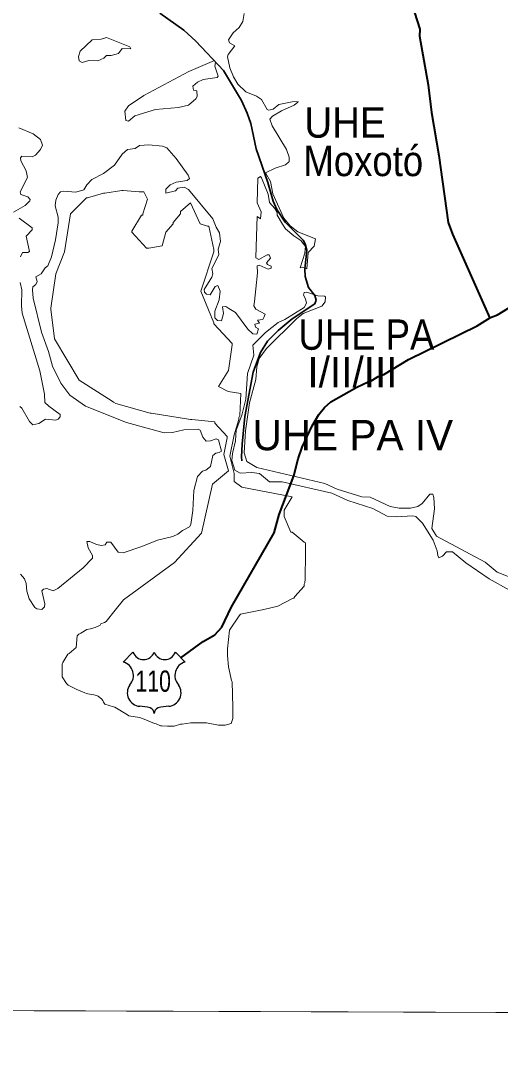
# Model space of a CAD drawing. Extents: x 553962 to 842807, y 8883888 to 9032388.
# Drawn here: x 580395 to 581976, y 8909822 to 8913255 of the extents above; entities that cross this region are included whole.
import ezdxf
from ezdxf.enums import TextEntityAlignment as Align

# ---------------------------------------------------------------- set-up
doc = ezdxf.new("R2010")
doc.units = 0
doc.header["$LTSCALE"] = 200
doc.linetypes.add('LONG_DASH_SHORT_DASH', pattern=[9.9, 6, -1.2, 1.5, -1.2])
doc.layers.add('6', color=7, linetype='Continuous', lineweight=13)

msp = doc.modelspace()

# ---------------------------------------------------------------- linework, layer by layer
at = {"layer": '6', "lineweight": 25}
for p, q in [((580732.9, 8911139.1), (580764.9, 8911171.1)), ((580904.8, 8911171.1), (580936.8, 8911139.1))]:
    msp.add_line(p, q, dxfattribs=at)
at = {"layer": '6'}
msp.add_line((574653.9, 8910009.3), (626625.7, 8909822.1), dxfattribs=at)
for points in [[(585645.8, 8921027.3), (574684.9, 8921064.7), (574653.9, 8910009.3), (585614.8, 8909969.8)], [(580677.4, 8913199.3), (580754.6, 8913169.1), (580757.7, 8913161.8), (580729.4, 8913163.2), (580717.7, 8913147), (580692.7, 8913140.2), (580677.9, 8913140.2), (580669, 8913131.7), (580648.6, 8913122.4), (580619.7, 8913123.6), (580597.1, 8913117.7), (580587.8, 8913122.8), (580585.2, 8913136.5), (580590.4, 8913155), (580629.9, 8913192.5), (580660.4, 8913193.7)], [(580749.7, 8912974.1), (580801.2, 8913008.5), (580948.9, 8913087.1), (581033.9, 8913124), (581037.3, 8913116.8), (581035.2, 8913105.4), (581045.7, 8913072.2), (581042.7, 8913067.9), (580996, 8913061.1), (580977.8, 8913051.8), (580962.2, 8913039.1), (580964.6, 8913025.5), (580976, 8913023.8), (580976.9, 8913004.7), (580972.7, 8912997.5), (580948.1, 8912976.6), (580915.4, 8912968.6), (580838.8, 8912961.7), (580770.9, 8912941.3), (580750.1, 8912923.1), (580741.6, 8912925.3), (580737.8, 8912956.3)]]:
    msp.add_lwpolyline(points, close=True, dxfattribs=at)
at = {"layer": '6', "linetype": 'LONG_DASH_SHORT_DASH', "lineweight": 35}
msp.add_lwpolyline([(580854, 8913279.9), (580932.2, 8913223.8), (580972.1, 8913187.7), (581063.2, 8913090.6), (581122.5, 8912991.5), (581142, 8912949.8), (581153.2, 8912915.6), (581171, 8912832.2), (581209.9, 8912721.7), (581227.6, 8912659.4), (581239.2, 8912631.8), (581266.5, 8912590.3), (581326.2, 8912531.5), (581332.6, 8912519.4), (581337.8, 8912498.5), (581331.8, 8912436.4), (581333.1, 8912411.1), (581343.9, 8912375), (581365.1, 8912348.2), (581368.5, 8912332.5), (581364.2, 8912321.3), (581289.9, 8912271.7), (581243.5, 8912233.1), (581208.6, 8912197.7), (581185.2, 8912160.5), (581161.6, 8912095.9), (581134.3, 8911949.1), (581124.7, 8911857.9), (581122.5, 8911815.6), (581124, 8911803.1)], dxfattribs=at)
at = {"layer": '6'}
for points in [[(581309.8, 8912988.2), (581309.8, 8912988.2), (581289.7, 8912987.7), (581245.5, 8912978.7), (581227.2, 8912963.4), (581212, 8912960.1), (581207.2, 8912962.6), (581188.9, 8912994.9), (581172.8, 8913005.9), (581137.1, 8913019.9), (581110.7, 8913045.9), (581096, 8913070), (581084, 8913099.8), (581076.8, 8913135.4), (581079.3, 8913144), (581100.6, 8913172.4), (581083.2, 8913182.3), (581079.8, 8913192.1), (581095.1, 8913214.9), (581115, 8913232.4), (581127.7, 8913252.7), (581131.6, 8913278.4)], [(581277.8, 8912788.2), (581279.5, 8912789.6), (581280, 8912805.1), (581271, 8912830.4), (581223.8, 8912908.6), (581216.6, 8912930.4), (581224.7, 8912939.7), (581254.8, 8912957.9), (581296.7, 8912976.6), (581308.1, 8912986.6), (581309.8, 8912988.2)], [(580388.5, 8912901.4), (580436.2, 8912882.3), (580460.3, 8912862.7), (580466.7, 8912844), (580460.3, 8912829.6), (580443.8, 8912811), (580432.7, 8912806.3), (580397.9, 8912807.9), (580394.1, 8912802.5), (580395.3, 8912793), (580413.2, 8912759.9), (580416.6, 8912737.9), (580392.8, 8912690.9), (580395.3, 8912681.4), (580418.7, 8912673.7), (580425.9, 8912664.7), (580424.9, 8912660.4), (580409.4, 8912645.7), (580371.5, 8912623.9)], [(580896.6, 8911553.8), (580912.7, 8911561), (580928, 8911573.3), (580951, 8911585.2), (580955.3, 8911593.3), (580962.1, 8911639.2), (580965.5, 8911704.7), (580977.3, 8911751.3), (580993.9, 8911768.7), (581005.5, 8911772.6), (581020.3, 8911784.5), (581028.3, 8911821), (581038.6, 8911828.7), (581049.6, 8911829.9), (581056.8, 8911835.1), (581046.7, 8911872.7), (581039.4, 8911875.4), (581020.8, 8911869.1), (581005.8, 8911868.2), (580995.2, 8911881.4), (580986.3, 8911903.8), (580980.3, 8911907.2), (580933.2, 8911905.1), (580895.8, 8911896.2), (580867.6, 8911895.4), (580743.7, 8911929.8), (580608.6, 8911983.8), (580557.2, 8912019.4), (580527, 8912059), (580499.4, 8912115), (580486.1, 8912163.4), (580463.7, 8912227.1), (580435.7, 8912339.3), (580433.1, 8912367.4), (580435.2, 8912376.6), (580444.6, 8912384.8), (580449.3, 8912394.6), (580444.7, 8912409.9), (580462.4, 8912419.7), (580475.2, 8912439.6), (580484.5, 8912446.8), (580496.3, 8912475.7), (580510, 8912532.2), (580518.5, 8912588.3), (580518.5, 8912607), (580508.3, 8912644.4), (580510.9, 8912663), (580518.7, 8912681.9), (580525.8, 8912690.7), (580535.5, 8912693.2), (580577, 8912689.8), (580577, 8912689.8), (580602.6, 8912697.5), (580612.9, 8912714.1), (580629, 8912731.5), (580667.3, 8912751.5), (580704.2, 8912779), (580728.9, 8912814.4), (580747.1, 8912830.5), (580772.6, 8912833.5), (580786.6, 8912842.8), (580816.8, 8912845.3), (580861.8, 8912841.5), (580876.7, 8912835.6), (580907.3, 8912800.7), (580946.8, 8912745.9), (580951.8, 8912734.5), (580944.1, 8912728.4), (580907.7, 8912722.4), (580888.1, 8912713.2), (580873.7, 8912699.1), (580873.7, 8912686.1), (580905.1, 8912693.7), (580912.8, 8912702.2), (580933.6, 8912706.4), (580948.5, 8912698.3), (581027.9, 8912601.9), (581039, 8912573.9), (581050.5, 8912555), (581053.4, 8912527.1), (581046.2, 8912500.8), (581047.9, 8912483.1), (581025, 8912437.1), (581027.9, 8912419.8), (581024.9, 8912409), (580999.5, 8912368.6), (581000.8, 8912359.3), (581007.1, 8912353), (581019.3, 8912350.8), (581035.6, 8912378), (581045.2, 8912381), (581052.5, 8912362.4), (581049.6, 8912334.3), (581034.7, 8912296.8), (581034.8, 8912275.2), (581043.2, 8912266.3), (581057.1, 8912265), (581063.6, 8912289.2), (581060.7, 8912310.8), (581070.9, 8912312.5), (581081.6, 8912305.8)], [(581366.5, 8912535.8), (581309.1, 8912558.6), (581283.7, 8912578.6), (581262.3, 8912603.9), (581262.3, 8912603.9), (581225.9, 8912683.5), (581218.3, 8912725.1), (581201.7, 8912753.5), (581233.6, 8912768.4), (581267.9, 8912779.9), (581277.8, 8912788.2)], [(581172.7, 8912543.7), (581175, 8912608.9), (581185.1, 8912601.8), (581187.7, 8912624), (581174.9, 8912654.7), (581176.2, 8912736.1), (581185.3, 8912741.2), (581189.3, 8912737.1), (581210.6, 8912682.6), (581215.3, 8912655.5), (581233.2, 8912635.8), (581239.9, 8912622.3), (581240, 8912613.3), (581258.5, 8912584.3)], [(580733.2, 8911343.8), (580902, 8911467.3), (580990.8, 8911564.2), (581027.1, 8911725.6), (581079.6, 8911770), (581064.5, 8911823.6), (581075.6, 8911879), (581075.6, 8911883.1), (581035.2, 8911927.5), (581035.2, 8911931.5), (580958.5, 8911939.6), (580954.5, 8911939.6), (580825.3, 8911959.8), (580821.3, 8911959.8), (580708.3, 8911992), (580700.2, 8911996.1), (580696.2, 8912000.1), (580587.3, 8912068.7), (580506.6, 8912206), (580494.4, 8912302.9), (580494.4, 8912306.9), (580510.6, 8912419.9), (580538.8, 8912492.6), (580559, 8912617.7), (580611.5, 8912670.2), (580615.5, 8912670.2), (580668, 8912686.4), (580672, 8912686.4), (580728.5, 8912694.4), (580732.5, 8912694.4), (580785, 8912690.4), (580793.1, 8912690.4), (580797.1, 8912690.4), (580801.1, 8912690.4), (580813.2, 8912666.2), (580797.1, 8912617.7), (580797.1, 8912613.7), (580793.1, 8912613.7), (580760.8, 8912561.2), (580760.8, 8912557.2), (580809.2, 8912504.7), (580813.2, 8912504.7), (580817.3, 8912504.7), (580861.7, 8912512.8), (580873.8, 8912557.2), (580898, 8912585.4), (580898, 8912589.5), (580922.2, 8912617.7), (580922.2, 8912621.8), (580922.2, 8912625.8), (580954.5, 8912654.1), (580986.8, 8912585.4), (581011, 8912577.4), (581015, 8912577.4), (581031.2, 8912500.7), (581031.2, 8912496.6), (581031.2, 8912492.6), (580988.2, 8912362.7), (581031.2, 8912258.5), (581031.2, 8912254.4), (581091.7, 8912189.8), (581091.7, 8912185.8), (581079.6, 8912101), (581047.3, 8912048.6)], [(580389.8, 8912603.1), (580432.7, 8912571.7), (580432.5, 8912565.6), (580412.3, 8912544.5), (580423.3, 8912493.2), (580418.2, 8912489.8), (580400.4, 8912490.6), (580394.5, 8912476.2)], [(581258.5, 8912584.3), (581268.3, 8912568.8), (581295.3, 8912545.3), (581319, 8912529.6), (581333.8, 8912510.2), (581332.8, 8912500.7)], [(581218.2, 8912471.5), (581214.4, 8912482.3), (581208, 8912482.9), (581179.6, 8912467.7), (581170.2, 8912473.2), (581172.7, 8912543.7)], [(581337.2, 8912437), (581338.1, 8912436.6), (581342.3, 8912490.1), (581362.3, 8912511), (581366.8, 8912535.7), (581366.5, 8912535.8)], [(581169.9, 8912369.9), (581175.8, 8912423.6), (581174.5, 8912446.3), (581181.3, 8912448.5), (581211, 8912434.9), (581220.8, 8912438.5), (581220.4, 8912445.1), (581208.9, 8912451.1), (581205.5, 8912456.7), (581218.2, 8912471.5), (581218.2, 8912471.5)], [(581332.8, 8912500.7), (581331.5, 8912488.3), (581315.9, 8912439.5), (581316.2, 8912439.6), (581316.2, 8912440.5)], [(581316.2, 8912439.6), (581324.1, 8912442.3), (581337.2, 8912437)], [(580393.2, 8912391), (580397.9, 8912367.4), (580397, 8912313.8), (580400, 8912290.1), (580457.8, 8912099.8), (580473.1, 8912022.4), (580474.8, 8911995.7), (580487.1, 8911983.3), (580524.9, 8911956.1), (580524.5, 8911947.6), (580518.1, 8911940), (580510.8, 8911937), (580476, 8911940), (580454.4, 8911926), (580434.4, 8911921.7), (580423.8, 8911932.8), (580398.7, 8911976.5), (580392.2, 8911981.7)], [(581196.1, 8912276.3), (581200.4, 8912287), (581169.9, 8912302.8), (581163.9, 8912314.7), (581165.4, 8912328.8), (581169.9, 8912369.9)], [(581135.5, 8911901.6), (581149.3, 8911994.6), (581170.2, 8912071.5), (581173.7, 8912113.4), (581181.2, 8912140.2), (581205.4, 8912173.1), (581304.6, 8912271.9), (581326.6, 8912288.6), (581388, 8912312.8), (581398.3, 8912327.2), (581399.7, 8912343.6), (581396.9, 8912346.6), (581374.1, 8912347), (581338.1, 8912359.7), (581329.6, 8912358.2), (581327, 8912349.8), (581333.7, 8912337.4), (581336.7, 8912322.7), (581329, 8912309.2), (581265.5, 8912268.8), (581244.2, 8912259.8), (581202.1, 8912226.9), (581160.5, 8912185.1), (581163.3, 8912151.7), (581142.6, 8912091.4), (581136.6, 8912006), (581124.1, 8911954.1), (581104.7, 8911903.6), (581102.9, 8911869.2), (581093, 8911827.2), (581091, 8911804.1), (581100.6, 8911772.3), (581118.2, 8911761.8), (581156.8, 8911764.7), (581182.7, 8911761.1), (581215.5, 8911733.5), (581257.2, 8911733.9), (581420.6, 8911696.1), (581473.7, 8911672.5), (581556.1, 8911645.9), (581603.5, 8911620.1), (581633.2, 8911618), (581687.3, 8911621.4), (581697.3, 8911618.8), (581720.2, 8911596.8), (581754.8, 8911541.3), (581768.5, 8911506.1), (581770.8, 8911491.1), (581773.4, 8911483.1), (581785.4, 8911488.5), (581798.7, 8911502.9), (581818.2, 8911502.4), (581863, 8911466.3), (581940, 8911413.8), (582006.9, 8911375.9)], [(581081.6, 8912305.8), (581103, 8912292.4), (581143.5, 8912237.3), (581160.1, 8912222.1), (581173.1, 8912220.7), (581178.4, 8912238.5), (581169, 8912243.4), (581167.3, 8912254.3), (581181.7, 8912256.8), (581176, 8912267.4), (581193.2, 8912269.3), (581196.1, 8912276.3)], [(581047.3, 8912048.6), (581079.2, 8912031.7), (581120.6, 8912025.3), (581117.4, 8911952), (581114.3, 8911945.6), (581114.3, 8911939.2), (581098.3, 8911888.2), (581083.9, 8911818.2), (581098.3, 8911761), (581098.3, 8911735.2), (581123.8, 8911716), (581289.6, 8911684.2)], [(582032.6, 8911409.3), (581966.1, 8911435.9), (581926.1, 8911468.6), (581766.4, 8911554.5), (581751, 8911579.8), (581759.2, 8911645), (581757, 8911682.3), (581753.9, 8911693), (581744.2, 8911692.6), (581718.2, 8911662.4), (581704.6, 8911652.6), (581679.8, 8911647.1), (581642.2, 8911646.8), (581613.1, 8911652.5), (581547.6, 8911683.5), (581519.6, 8911684), (581438.5, 8911709), (581397.4, 8911727.8), (581173.1, 8911780.9), (581140.4, 8911800.9), (581132.1, 8911829.1), (581135.5, 8911901.6)], [(581091.6, 8911074.3), (581090.1, 8911078.7), (581079.7, 8911123.2), (581076.8, 8911160.2), (581076.8, 8911182.4), (581082.7, 8911244.6), (581115.3, 8911292), (581119.7, 8911296.5), (581196.7, 8911312.8), (581242.6, 8911323.1), (581291.5, 8911348.3), (581295.9, 8911349.8), (581298.9, 8911355.7), (581330, 8911389.8), (581330, 8911395.7), (581331.5, 8911400.1), (581332.9, 8911412), (581332.9, 8911423.8), (581334.4, 8911487.5), (581334.4, 8911492), (581334.4, 8911496.4), (581334.4, 8911532), (581330, 8911534.9), (581290, 8911567.5), (581285.5, 8911567.5), (581263.3, 8911619.3), (581263.3, 8911640.1), (581289.6, 8911684.2)], [(581289.6, 8911684.2), (581263.3, 8911640.1), (581263.3, 8911619.3), (581285.5, 8911567.5), (581290, 8911567.5), (581330, 8911534.9), (581334.4, 8911532), (581334.4, 8911496.4), (581334.4, 8911492), (581334.4, 8911487.5), (581332.9, 8911423.8), (581332.9, 8911412), (581331.5, 8911400.1), (581330, 8911395.7), (581330, 8911389.8), (581298.9, 8911355.7), (581295.9, 8911349.8), (581291.5, 8911348.3), (581242.6, 8911323.1), (581196.7, 8911312.8), (581119.7, 8911296.5), (581115.3, 8911292), (581082.7, 8911244.6), (581076.8, 8911182.4), (581076.8, 8911160.2), (581079.7, 8911123.2), (581090.1, 8911078.7), (581091.6, 8911074.3)], [(580394, 8911428.9), (580406.8, 8911413.6), (580413.2, 8911398.7), (580415.3, 8911373.2), (580422.9, 8911347.7), (580441.2, 8911319.3), (580447.6, 8911315), (580464.1, 8911312.5), (580473, 8911320.9), (580474.3, 8911331.5), (580464.2, 8911373.9), (580469.6, 8911380), (580480.7, 8911382.1), (580501.4, 8911373.7), (580516.9, 8911381.3), (580601.1, 8911449.4), (580631.4, 8911481.8), (580631.6, 8911490.3), (580617.5, 8911516), (580612.5, 8911537.2), (580623.1, 8911537.2), (580644.2, 8911526.6), (580661.3, 8911523.2), (580673.6, 8911525.3), (580678.7, 8911535.1), (580691.8, 8911535.1), (580716.5, 8911501.6), (580732.2, 8911499.4), (580794.7, 8911520.2), (580845.5, 8911541.4), (580896.6, 8911553.8)], [(580733.2, 8911343.8), (580706.6, 8911309.8), (580677, 8911272.8), (580671.1, 8911269.8), (580659.2, 8911265.3), (580656.3, 8911260.9), (580640, 8911253.5), (580635.5, 8911252), (580625.2, 8911249.1), (580613.3, 8911246.1), (580592.6, 8911234.2), (580586.7, 8911231.3), (580580.7, 8911225.4), (580577.8, 8911186.8), (580554.1, 8911167.6), (580549.7, 8911164.6), (580533.4, 8911138), (580531.9, 8911133.5), (580531.9, 8911123.2), (580531.9, 8911095), (580531.9, 8911090.6), (580545.2, 8911068.4), (580551.1, 8911062.4), (580582.2, 8911047.6), (580588.2, 8911044.7), (580592.6, 8911043.2), (580605.9, 8911037.2), (580611.8, 8911035.8), (580616.3, 8911034.3), (580635.5, 8911031.3), (580640, 8911029.8), (580650.3, 8911026.9), (580656.3, 8911021), (580660.7, 8911018), (580665.1, 8911012.1), (580668.1, 8911006.2), (580672.6, 8911000.2), (580700.7, 8910991.3), (580705.1, 8910989.9), (580746.6, 8910964.7), (580751, 8910961.7), (580786.6, 8910955.8), (580796.9, 8910952.8), (580835.4, 8910936.5), (580841.3, 8910935.1), (580856.2, 8910929.1), (580860.6, 8910929.1), (580878.4, 8910927.7), (580884.3, 8910927.7), (580894.7, 8910927.7), (580900.6, 8910927.7), (580921.3, 8910933.6), (580927.2, 8910933.6), (580955.3, 8910938), (580967.2, 8910938), (581007.2, 8910938), (581047.2, 8910930.6), (581069.4, 8910930.6), (581088.6, 8910936.5), (581094.5, 8910952.8), (581094.5, 8910957.3), (581094.5, 8910994.3), (581093.1, 8911026.9), (581093.1, 8911032.8), (581091.6, 8911074.3)], [(581091.6, 8911074.3), (581093.1, 8911032.8), (581093.1, 8911026.9), (581094.5, 8910994.3), (581094.5, 8910957.3), (581094.5, 8910952.8), (581088.6, 8910936.5), (581069.4, 8910930.6), (581047.2, 8910930.6), (581007.2, 8910938), (580967.2, 8910938), (580955.3, 8910938), (580927.2, 8910933.6), (580921.3, 8910933.6), (580900.6, 8910927.7), (580894.7, 8910927.7), (580884.3, 8910927.7), (580878.4, 8910927.7), (580860.6, 8910929.1), (580856.2, 8910929.1), (580841.3, 8910935.1), (580835.4, 8910936.5), (580796.9, 8910952.8), (580786.6, 8910955.8), (580751, 8910961.7), (580746.6, 8910964.7), (580705.1, 8910989.9), (580700.7, 8910991.3), (580672.6, 8911000.2), (580668.1, 8911006.2), (580665.1, 8911012.1), (580660.7, 8911018), (580656.3, 8911021), (580650.3, 8911026.9), (580640, 8911029.8), (580635.5, 8911031.3), (580616.3, 8911034.3), (580611.8, 8911035.8), (580605.9, 8911037.2), (580592.6, 8911043.2), (580588.2, 8911044.7), (580582.2, 8911047.6), (580551.1, 8911062.4), (580545.2, 8911068.4), (580531.9, 8911090.6), (580531.9, 8911095), (580531.9, 8911123.2), (580531.9, 8911133.5), (580533.4, 8911138), (580549.7, 8911164.6), (580554.1, 8911167.6), (580577.8, 8911186.8), (580580.7, 8911225.4), (580586.7, 8911231.3), (580592.6, 8911234.2), (580613.3, 8911246.1), (580625.2, 8911249.1), (580635.5, 8911252), (580640, 8911253.5), (580656.3, 8911260.9), (580659.2, 8911265.3), (580671.1, 8911269.8), (580677, 8911272.8), (580706.6, 8911309.8), (580733.2, 8911343.8)]]:
    msp.add_lwpolyline(points, dxfattribs=at)
at = {"layer": '6', "lineweight": 40}
for points in [[(581692.8, 8913282), (581711.4, 8913227.6), (581709.7, 8913204.2), (581738.2, 8913043.9), (581749.4, 8912952.6), (581773.3, 8912810.4), (581804.3, 8912589.4), (581818.2, 8912550.3), (581941.2, 8912274)], [(581088.7, 8911319.2), (581230.6, 8911565.6), (581246.6, 8911626.2), (581295.9, 8911753.5), (581309.3, 8911809.4), (581322.7, 8911848.3), (581355.5, 8911918.2), (581377.7, 8911955.6), (581396.6, 8911978.5), (581417.4, 8911997.1), (581502.6, 8912046.4), (581540.6, 8912063.6), (581547.6, 8912064.2), (581573.9, 8912081.4), (581591.7, 8912087.9), (581673.8, 8912137.2), (581899.5, 8912248.7), (581943.6, 8912275.5), (581967, 8912284.7), (582035.6, 8912326.1)], [(580922.7, 8911153.1), (580996.2, 8911207.1), (581034.8, 8911228.8), (581058, 8911254.4), (581088.7, 8911319.2)]]:
    msp.add_lwpolyline(points, dxfattribs=at)
at = {"layer": '6', "lineweight": 25}
for centre, radius, start, end in [((580799.9, 8911184.5), 37.4, 200.9593, 339.0407), ((580869.8, 8911184.5), 37.4, 200.9593, 339.0407), ((580720.5, 8911094.7), 46.1, 317.5721, 74.3689), ((580949.2, 8911094.7), 46.1, 105.6277, 222.4279), ((580791.2, 8911037.7), 44.9, 144.7373, 264.6578), ((580878.5, 8911037.7), 44.9, 275.3422, 35.2627), ((580786.8, 8910875), 118, 72.8937, 89.9006), ((580882.9, 8910875), 118, 90.0994, 107.1063), ((580816, 8910969.7), 18.9, 357.6934, 72.9296), ((580853.7, 8910969.7), 18.9, 107.0704, 182.3065)]:
    msp.add_arc(centre, radius, start, end, dxfattribs=at)

# ---------------------------------------------------------------- texts
at = {"layer": '6'}
for s, height, width, p in [('UHE', 100, 0.95, (581464.1, 8912869.1)), ('Moxotó', 100, 0.9, (581524.5, 8912742.3)), ('UHE PA', 100, 0.9, (581534.8, 8912169.4)), ('110', 70, 0.75, (580831.6, 8911041.1))]:
    msp.add_text(s, height=height, dxfattribs=dict(at, width=width)).set_placement(p, align=Align.CENTER)
for s, p in [('I/II/III', (581488.8, 8912045.7)), ('UHE PA IV', (581490, 8911837.9))]:
    msp.add_text(s, height=100, dxfattribs=at).set_placement(p, align=Align.CENTER)

doc.saveas('drawing.dxf')
